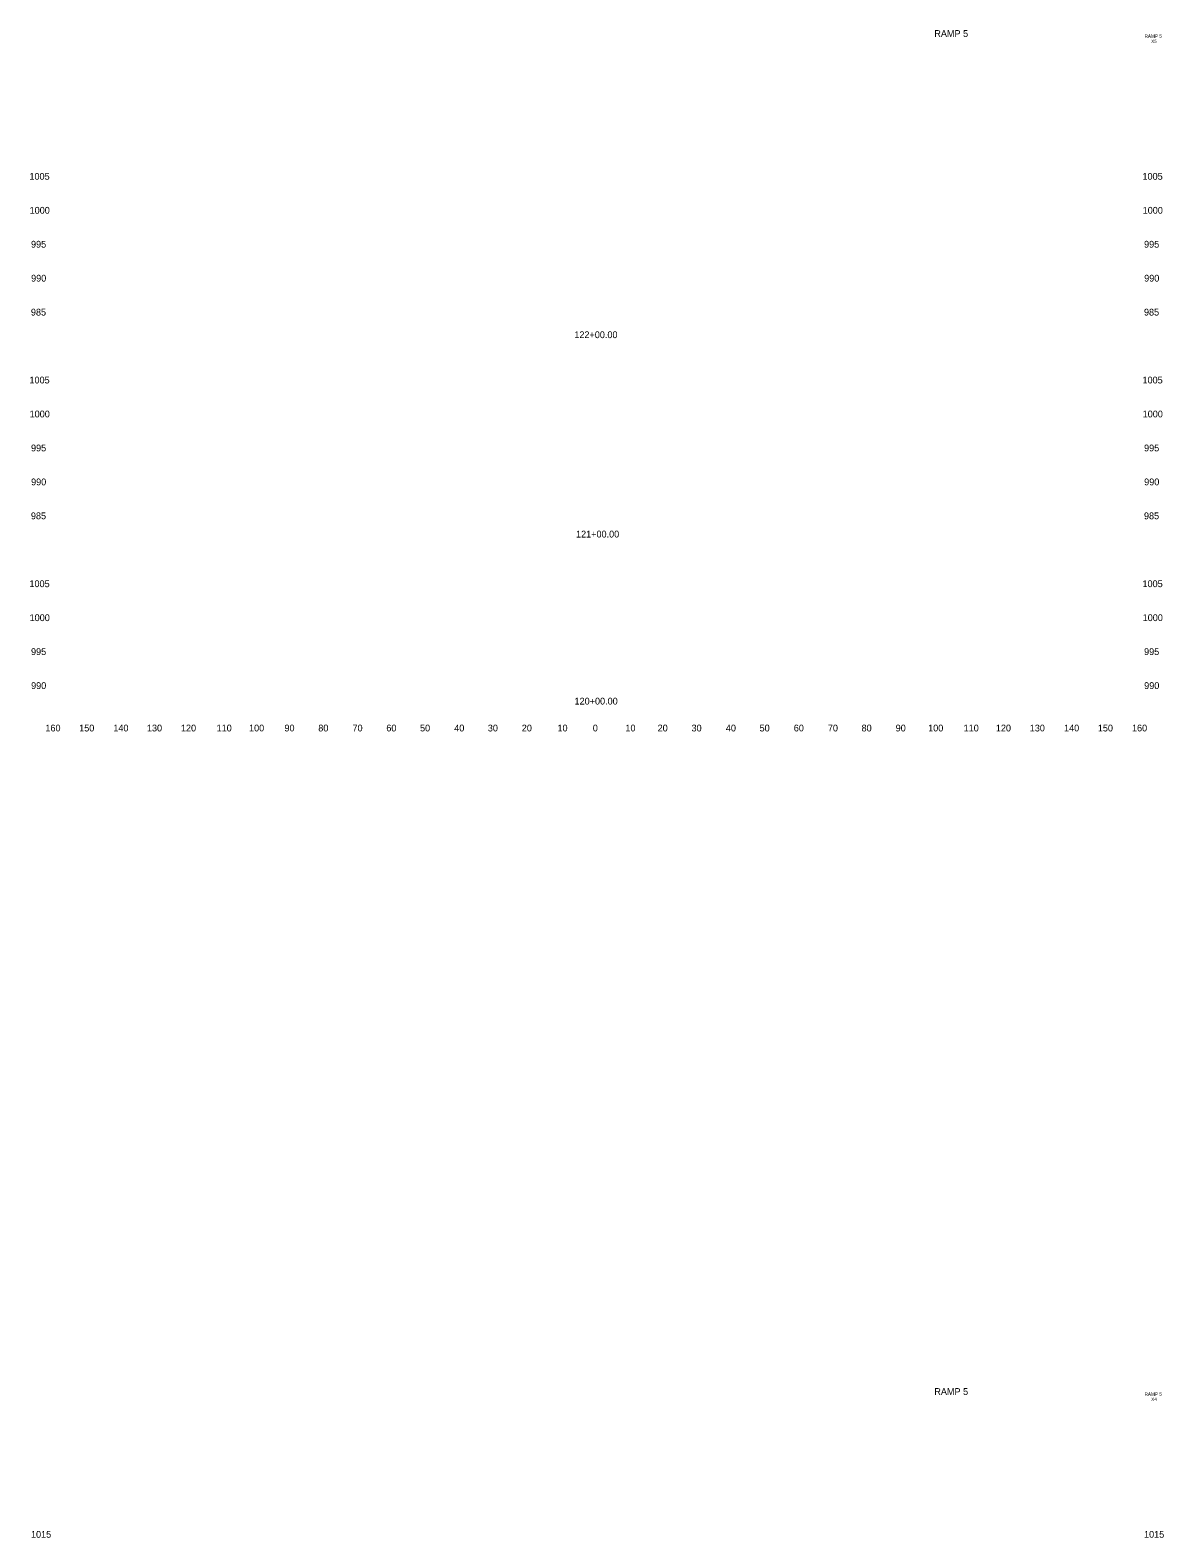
# Model space of a CAD drawing. Extents: x 4994 to 5842, y 4997 to 8804.
# Drawn here: x 4993.6 to 5327.5, y 6360 to 6804.1 of the extents above; entities that cross this region are included whole.
import ezdxf

# ---------------------------------------------------------------- set-up
doc = ezdxf.new("R2010")
doc.units = 0
for name, color, linetype in [('CLS_Search_Dist', 7, 'Continuous'), ('RD_XE_Ground', 7, 'Continuous'), ('UC_PD_Text', 7, 'Continuous')]:
    doc.layers.add(name, color=color, linetype=linetype)

msp = doc.modelspace()

# ---------------------------------------------------------------- texts
at = {"layer": 'CLS_Search_Dist'}
for s, p in [('1005', (4993.4, 6760)), ('1005', (5321.2, 6760)), ('1000', (4993.44, 6750)), ('1000', (5321.24, 6750)), ('995', (4993.86, 6740)), ('995', (5321.66, 6740)), ('990', (4993.89, 6730)), ('990', (5321.69, 6730)), ('985', (4993.83, 6720)), ('985', (5321.63, 6720)), ('1005', (4993.4, 6700)), ('1005', (5321.2, 6700)), ('1000', (4993.44, 6690)), ('1000', (5321.24, 6690)), ('995', (4993.86, 6680)), ('995', (5321.66, 6680)), ('990', (4993.89, 6670)), ('990', (5321.69, 6670)), ('985', (4993.83, 6660)), ('985', (5321.63, 6660)), ('1005', (4993.4, 6640)), ('1005', (5321.2, 6640)), ('1000', (4993.44, 6630)), ('1000', (5321.24, 6630)), ('995', (4993.86, 6620)), ('995', (5321.66, 6620)), ('990', (4993.89, 6610)), ('990', (5321.69, 6610)), ('160', (4998.1, 6597.5)), ('150', (5008.04, 6597.5)), ('140', (5018.1, 6597.5)), ('130', (5027.99, 6597.5)), ('120', (5038.01, 6597.5)), ('110', (5048.51, 6597.5)), ('100', (5058.07, 6597.5)), ('90', (5068.5, 6597.5)), ('80', (5078.46, 6597.5)), ('70', (5088.54, 6597.5)), ('60', (5098.5, 6597.5)), ('50', (5108.43, 6597.5)), ('40', (5118.5, 6597.5)), ('30', (5128.39, 6597.5)), ('20', (5138.4, 6597.5)), ('10', (5148.91, 6597.5)), ('0', (5159.3, 6597.5)), ('0', (5159.3, 6597.5)), ('10', (5168.91, 6597.5)), ('20', (5178.4, 6597.5)), ('30', (5188.39, 6597.5)), ('40', (5198.5, 6597.5)), ('50', (5208.43, 6597.5)), ('60', (5218.5, 6597.5)), ('70', (5228.54, 6597.5)), ('80', (5238.46, 6597.5)), ('90', (5248.5, 6597.5)), ('100', (5258.07, 6597.5)), ('110', (5268.51, 6597.5)), ('120', (5278.01, 6597.5)), ('130', (5287.99, 6597.5)), ('140', (5298.1, 6597.5)), ('150', (5308.04, 6597.5)), ('160', (5318.1, 6597.5)), ('1015', (4993.85, 6360)), ('1015', (5321.65, 6360))]:
    msp.add_text(s, height=2, dxfattribs=at).set_placement(p)
at = {"layer": 'RD_XE_Ground'}
for s, p in [('122+00.00', (5153.87, 6713.34)), ('121+00.00', (5154.37, 6654.62)), ('120+00.00', (5153.93, 6605.42))]:
    msp.add_text(s, height=2, dxfattribs=at).set_placement(p)
at = {"layer": 'UC_PD_Text'}
for s, height, p in [('RAMP 5', 2, (5259.89, 6802.06)), ('RAMP 5', 1, (5321.78, 6801.8)), ('X5', 1, (5323.74, 6800.3)), ('RAMP 5', 2, (5259.89, 6402.06)), ('RAMP 5', 1, (5321.78, 6401.8)), ('X4', 1, (5323.74, 6400.3))]:
    msp.add_text(s, height=height, dxfattribs=at).set_placement(p)

doc.saveas('drawing.dxf')
